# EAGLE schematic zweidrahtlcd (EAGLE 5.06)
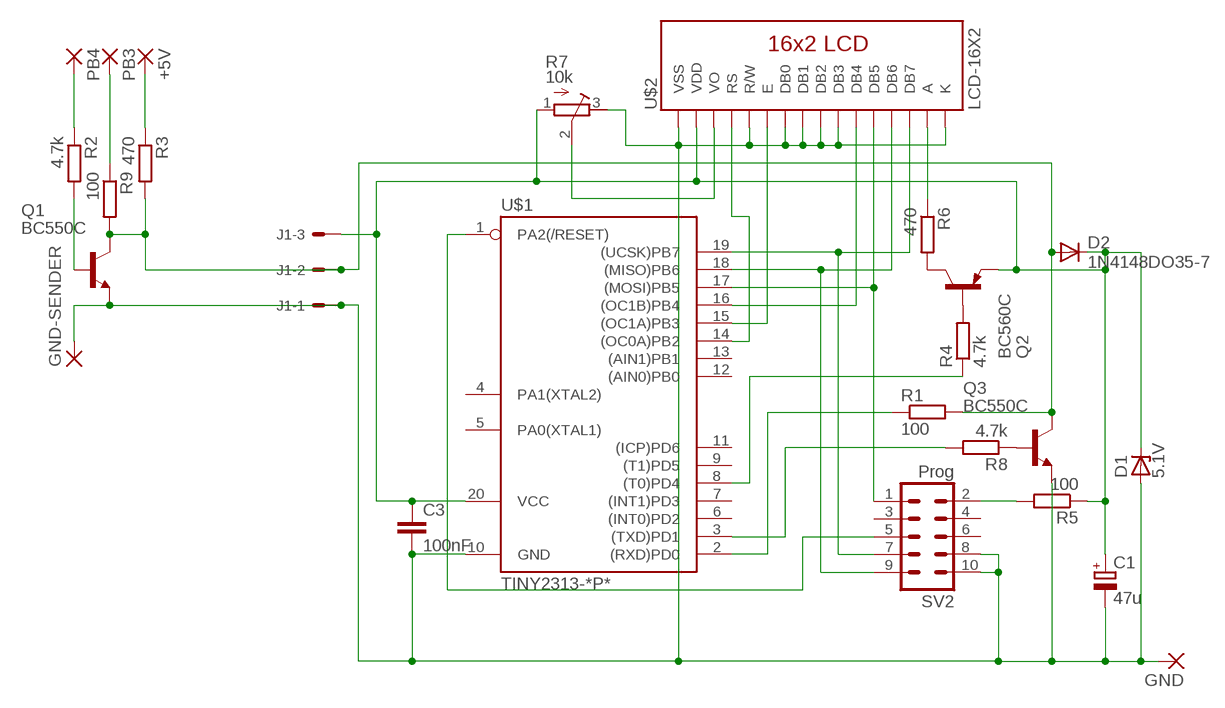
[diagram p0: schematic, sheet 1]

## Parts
+5V  WIREPAD3,81/1,1  [3,81/1,1]
C1  47u  CPOL-EUE3.5-8  [E3,5-8]
C3  100nF  C-EU050-024X044  [C050-024X044]
D1  5.1V  ZENER-DIODEC1702-15  [C1702-15]
D2  1N4148DO35-7  [DO35-7]
GND  WIREPAD3,81/1,1  [3,81/1,1]
GND-SENDER  WIREPAD3,81/1,1  [3,81/1,1]
J1  22-27-2031-03  [6410-03]
PB3  WIREPAD3,81/1,1  [3,81/1,1]
PB4  WIREPAD3,81/1,1  [3,81/1,1]
Q1  BC550C  [TO92-EBC]
Q2  BC560C  [TO92-EBC]
Q3  BC550C  [TO92-EBC]
R1  100  R-EU_0204/7  [0204/7]
R2  4.7k  R-EU_0204/7  [0204/7]
R3  470  R-EU_0204/7  [0204/7]
R4  4.7k  R-EU_0204/7  [0204/7]
R5  100  R-EU_0204/7  [0204/7]
R6  470  R-EU_0204/7  [0204/7]
R7  10k  R-TRIMM3339P  [RTRIM3339P]
R8  4.7k  R-EU_0204/7  [0204/7]
R9  100  R-EU_0204/7  [0204/7]
SV2  Prog  ML10  [ML10]
U$1  TINY2313-*P*  [DIL20]
U$2  LCD-16X2  [LCD-16X2]

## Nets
GND: C1.- C3.2 D1.A GND-SENDER.1(P) GND.1(P) J1.1 Q1.E Q3.E R7.3(A) SV2.8 SV2.10 U$1.10(GND) U$2.1(VSS) U$2.5(R/W) U$2.7(DB0) U$2.8(DB1) U$2.9(DB2) U$2.10(DB3) U$2.16(K)
N$1: SV2.1 U$1.17((MOSI)PB5) U$2.12(DB5)
N$2: +5V.1(P) R3.1
N$3: SV2.9 U$1.18((MISO)PB6) U$2.13(DB6)
N$4: R8.2 U$1.3((TXD)PD1)
N$5: R1.1 U$1.2((RXD)PD0)
N$6: Q1.B R2.2
N$7: PB4.1(P) R2.1
N$8: Q2.C R6.2
N$9: U$1.14((OC0A)PB2) U$2.4(RS)
N$10: R5.2 SV2.2
N$11: SV2.7 U$1.19((UCSK)PB7) U$2.14(DB7)
N$12: R4.1 U$1.8((T0)PD4)
N$13: Q2.B R4.2
N$14: U$1.15((OC1A)PB3) U$2.6(E)
N$15: SV2.5 U$1.1(PA2(/RESET))
N$16: R6.1 U$2.15(A)
N$17: U$1.16((OC1B)PB4) U$2.11(DB4)
N$18: Q3.B R8.1
N$19: R7.2(S) U$2.3(VO)
N$20: D2.A J1.2 Q1.C Q3.C R1.2 R3.2 R9.2
N$21: PB3.1(P) R9.1
VCC: C1.+ C3.1 D1.C D2.C J1.3 Q2.E R5.1 R7.1(E) U$1.20(VCC) U$2.2(VDD)
Unconnected: SV2.3 SV2.4 SV2.6 U$1.4(PA1(XTAL2)) U$1.5(PA0(XTAL1)) U$1.6((INT0)PD2) U$1.7((INT1)PD3) U$1.9((T1)PD5) U$1.11((ICP)PD6) U$1.12((AIN0)PB0) U$1.13((AIN1)PB1)

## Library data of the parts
+5V GND GND-SENDER PB3 PB4 = wirepad:WIREPAD: Wire PAD connect wire on PCB
C1 = rcl:CPOL-EU: POLARIZED CAPACITOR, European symbol
C3 = rcl:C-EU: CAPACITOR, European symbol
D1 = diode:ZENER-DIODE: Z-Diode
D2 = diode:1N4148: DIODE
J1 = con-molex:22-?-03: CONNECTOR wire to board 2.54 mm (.1 inch) pitch header
Q1 Q3 = transistor-npn:BC550*: NPN Transistor
Q2 = transistor-pnp:BC560*: PNP Transistror
R1-R6 R8 R9 = rcl:R-EU_: RESISTOR, European symbol
R7 = resistor:R-TRIMM: Trimm resistor
SV2 = con-harting-ml:ML10: HARTING
U$1 = avr-6:TINY2313*: Atmel Tiny2313 2K Flash, 128 bytes EEPROM, 128 bytes RAM
U$2 = SparkFun:LCD-16X2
